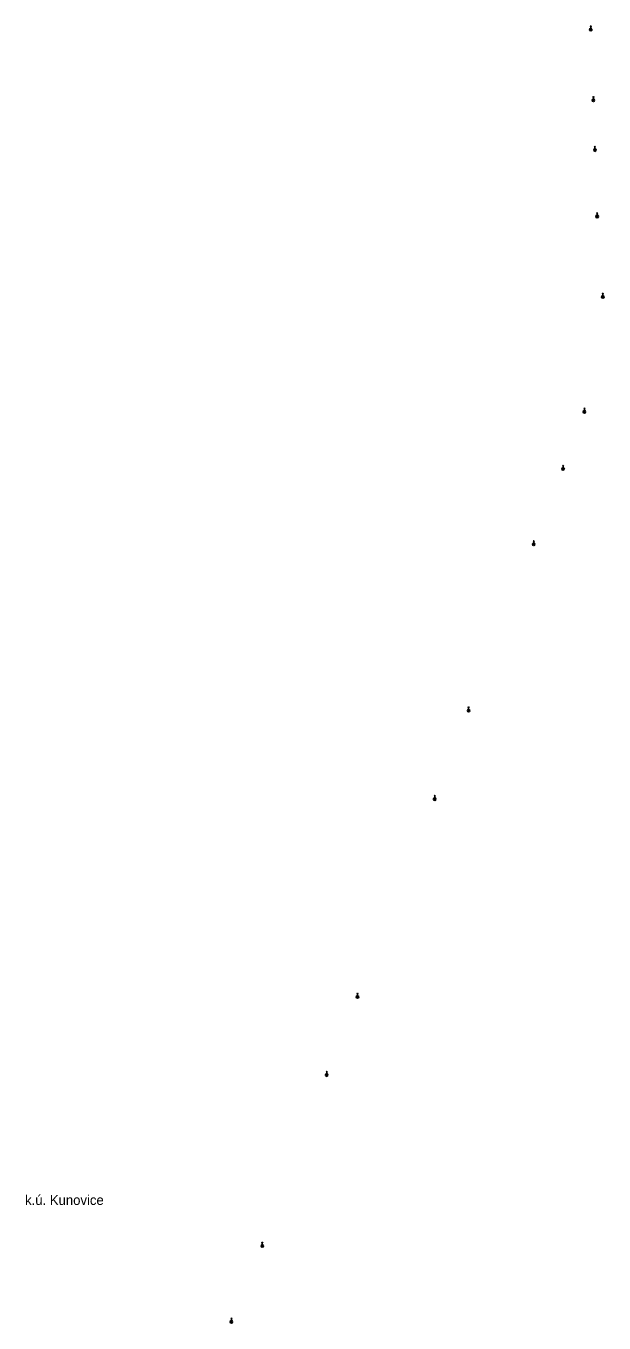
# Model space of a CAD drawing. Extents: x -540161 to -537510, y -1183993 to -1180459.
# Drawn here: x -538930.1 to -538753.1, y -1182189.1 to -1181791.8 of the extents above; entities that cross this region are included whole.
import ezdxf

# ---------------------------------------------------------------- set-up
doc = ezdxf.new("R2010")
doc.units = 0
doc.layers.add('NÁZEV_K_Ú', color=7, linetype='Continuous')
doc.layers.add('ZN_BP', color=7, linetype='Continuous')

msp = doc.modelspace()

# ---------------------------------------------------------------- linework, layer by layer
at = {"layer": 'ZN_BP'}
for p, q in [((-538757.435, -1181793.234), (-538756.906, -1181792.706)), ((-538756.906, -1181793.238), (-538757.435, -1181792.706)), ((-538757.17, -1181792.595), (-538757.17, -1181791.845)), ((-538756.655, -1181814.884), (-538756.126, -1181814.356)), ((-538756.126, -1181814.888), (-538756.655, -1181814.356)), ((-538756.39, -1181814.245), (-538756.39, -1181813.495)), ((-538756.175, -1181830.144), (-538755.646, -1181829.616)), ((-538755.646, -1181830.148), (-538756.175, -1181829.616)), ((-538755.91, -1181829.505), (-538755.91, -1181828.755)), ((-538755.495, -1181850.464), (-538754.966, -1181849.936)), ((-538754.966, -1181850.468), (-538755.495, -1181849.936)), ((-538755.23, -1181849.825), (-538755.23, -1181849.075)), ((-538753.755, -1181875.094), (-538753.226, -1181874.566)), ((-538753.226, -1181875.098), (-538753.755, -1181874.566)), ((-538753.49, -1181874.455), (-538753.49, -1181873.705)), ((-538759.385, -1181910.294), (-538758.856, -1181909.766)), ((-538758.856, -1181910.298), (-538759.385, -1181909.766)), ((-538759.12, -1181909.655), (-538759.12, -1181908.905)), ((-538765.905, -1181927.814), (-538765.376, -1181927.286)), ((-538765.376, -1181927.818), (-538765.905, -1181927.286)), ((-538765.64, -1181927.175), (-538765.64, -1181926.425)), ((-538774.905, -1181950.914), (-538774.376, -1181950.386)), ((-538774.376, -1181950.918), (-538774.905, -1181950.386)), ((-538774.64, -1181950.275), (-538774.64, -1181949.525)), ((-538794.835, -1182001.814), (-538794.306, -1182001.286)), ((-538794.306, -1182001.818), (-538794.835, -1182001.286)), ((-538794.57, -1182001.175), (-538794.57, -1182000.425)), ((-538805.215, -1182028.924), (-538804.686, -1182028.396)), ((-538804.686, -1182028.928), (-538805.215, -1182028.396)), ((-538804.95, -1182028.285), (-538804.95, -1182027.535)), ((-538828.845, -1182089.484), (-538828.316, -1182088.956)), ((-538828.316, -1182089.488), (-538828.845, -1182088.956)), ((-538828.58, -1182088.845), (-538828.58, -1182088.095)), ((-538838.285, -1182113.454), (-538837.756, -1182112.926)), ((-538837.756, -1182113.458), (-538838.285, -1182112.926)), ((-538838.02, -1182112.815), (-538838.02, -1182112.065)), ((-538857.985, -1182165.784), (-538857.456, -1182165.256)), ((-538857.456, -1182165.788), (-538857.985, -1182165.256)), ((-538857.72, -1182165.145), (-538857.72, -1182164.395)), ((-538867.455, -1182189.014), (-538866.926, -1182188.486)), ((-538866.926, -1182189.018), (-538867.455, -1182188.486)), ((-538867.19, -1182188.375), (-538867.19, -1182187.625))]:
    msp.add_line(p, q, dxfattribs=at)
for points in [[(-538757.295, -1181792.095), (-538757.17, -1181791.845), (-538757.045, -1181792.095)], [(-538756.515, -1181813.745), (-538756.39, -1181813.495), (-538756.265, -1181813.745)], [(-538756.035, -1181829.005), (-538755.91, -1181828.755), (-538755.785, -1181829.005)], [(-538755.355, -1181849.325), (-538755.23, -1181849.075), (-538755.105, -1181849.325)], [(-538753.615, -1181873.955), (-538753.49, -1181873.705), (-538753.365, -1181873.955)], [(-538759.245, -1181909.155), (-538759.12, -1181908.905), (-538758.995, -1181909.155)], [(-538765.765, -1181926.675), (-538765.64, -1181926.425), (-538765.515, -1181926.675)], [(-538774.765, -1181949.775), (-538774.64, -1181949.525), (-538774.515, -1181949.775)], [(-538794.695, -1182000.675), (-538794.57, -1182000.425), (-538794.445, -1182000.675)], [(-538805.075, -1182027.785), (-538804.95, -1182027.535), (-538804.825, -1182027.785)], [(-538828.705, -1182088.345), (-538828.58, -1182088.095), (-538828.455, -1182088.345)], [(-538838.145, -1182112.315), (-538838.02, -1182112.065), (-538837.895, -1182112.315)], [(-538857.845, -1182164.645), (-538857.72, -1182164.395), (-538857.595, -1182164.645)], [(-538867.315, -1182187.875), (-538867.19, -1182187.625), (-538867.065, -1182187.875)]]:
    msp.add_lwpolyline(points, dxfattribs=at)
for centre in [(-538757.17, -1181792.97), (-538756.39, -1181814.62), (-538755.91, -1181829.88), (-538755.23, -1181850.2), (-538753.49, -1181874.83), (-538759.12, -1181910.03), (-538765.64, -1181927.55), (-538774.64, -1181950.65), (-538794.57, -1182001.55), (-538804.95, -1182028.66), (-538828.58, -1182089.22), (-538838.02, -1182113.19), (-538857.72, -1182165.52), (-538867.19, -1182188.75)]:
    msp.add_circle(centre, 0.375, dxfattribs=at)

# ---------------------------------------------------------------- texts
at = {"layer": 'NÁZEV_K_Ú'}
msp.add_text('k.ú. Kunovice', height=3, dxfattribs=at).set_placement((-538930.348, -1182152.95))

doc.saveas('drawing.dxf')
